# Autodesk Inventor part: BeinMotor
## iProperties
Author: Standard
Created: 2002-11
Part Number: BeinMotor
Material: Standard
Document SubType Name: Modellieren
Designer: Standard
Control State: 0
Master: False
Checked Out: False
PropertySet Name: Design Tracking Control
Shininess: 20.0
Angle Display Precision: 2
Document Length Units: 11269
Document Angle Units: 11283
Document Time Units: 11279
Document Mass Units: 11290
Document Length Units Precision: 3
Document Angle Units Precision: 2
Compacted: False
PropertySet Name: _Private Model Information
Density: 0.0
Volumn: 0.0
Area: 0.0
PropertySet Name: Model Information
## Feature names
1. Extrusion1
2. Extrusion2
